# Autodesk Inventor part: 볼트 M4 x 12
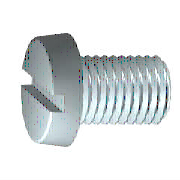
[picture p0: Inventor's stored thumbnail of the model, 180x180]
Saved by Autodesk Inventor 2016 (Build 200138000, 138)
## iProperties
Created: 2012-02
Part Number: 볼트 M4 x 12
Material: 강철, 연강
Description: 6각머리 태핑 나사
Document SubType Name: Modeling
Standard: KS B 1021
Designer: mduedu
Standards Organization: KS
Language: ko-KR
Size Designation: A  M 4 x 12
Categories: <MemberInstance><Categories><Category DisplayName="조임쇠" InternalName="e4da775c-781d-43d5-af7c-5136215cf5a6" Mnemonic="FSTN"><Category DisplayName="볼트" InternalN
Density: 1 g/cm^3
Appearance: 강철
IsCustomPart: 0
Author: mduedu
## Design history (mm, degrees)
body "Solid1"
revolve "본체" stored, may be unused: angle "d8" = 90 deg
sketch "스케치2"
  geometry: L1 (0, 0)-(0, 3.273) reference; L2 (-3.5, 0.6)-(3.5, 0.6); L3 (3.5, 0.6)-(3.5, -0.6); L4 (3.5, -0.6)-(-3.5, -0.6); L5 (-3.5, -0.6)-(-3.5, 0.6); L6 (-3.5, 0)-(3.5, 0); L7 (0, 0.6)-(0, -0.6); C1 r 3.5 at (0, 0) reference; 1 further point
  constraints: 12 end point, 5 midpoint, 2 parallel, 1 collinear, 1 horizontal, 1 perpendicular
  dimensions: "d11" = 1.2 distance of L4.end L2.start (= SBR); "d12" = 7 distance of L2.start L2.end (= KOD)
fillet "모깎기1" dims "d14" = 0.2 (= RR)
extrude "슬롯" cut sketch "스케치2" distance "d19" = 1.1 (= STI); taper "d20" = 0 deg
feature "스레드" dims "d15" = 10.6 (= GEL), "d16" = 0
chamfer "모따기1" distance "d17" = 0.42941 (= -0.5 x SPD + 0.5 x GD); stored, may be unused: second distance "d18" = 0.42952 (computed from GUL), angle "d36" = 45 deg
workplane "Work Plane1"
sketch "스케치1"
  geometry: L1 (-2.6, 0)-(12, 0); L2 (12, 0)-(12, 2); L3 (12, 2)-(1.4, 2); L4 (1.4, 2)-(0.97, 1.785); L5 (0.97, 1.785)-(0, 1.785); L6 (0, 1.785)-(0, 3.5); L7 (-5.52, 0)-(14.92, 0) reference; L8 (0, -0.7)-(0, 4.2) reference; L9 (-2.6, 0)-(-2.6, 3.273); L10 (0, 3.5)-(-2.6, 3.273); L11 (1.4, 2)-(0, 2)
  constraints: 18 end point, 4 parallel, 2 collinear, 2 perpendicular, 1 horizontal, 1 point on line
  dimensions: "d0" = 12 distance between parallel lines of L2 L6 (= NLG); "d1" = 10.6 distance from line of L3.end L2 (= GEL); "d2" = 0.42952 horizontal distance of L4.end L3.end (computed from GAL); "d3" = 2.6 distance from line of L1.start L6 (= KOH); "d4" = 4 diameter of L3 L1 (= GD); "d5" = 3.5705 diameter of L5 L1 (= BDM); "d9" = 7 diameter of L6.end L1 (= KOD); "d10" = 5 deg angle of L10 L1 (= KEWI)
other parameters: "GD" = 4 (= NND) [user parameter; used in 2 equation terms], "NLG" = 12 [user parameter; used in 1 equation term], "GEL" = 10.6 [user parameter; used in 2 equation terms], "KOD" = 7 [user parameter; used in 2 equation terms], "KOH" = 2.6 [user parameter; used in 1 equation term], "GAL" = 0.42941 (= 0.61345 x PTC) [user parameter; used in 1 equation term], "SPD" = 3.14117 (= NND - 1.2269 x PTC) [user parameter; used in 1 equation term], "BDM" = 3.5705 [user parameter; used in 1 equation term], "GUL" = 0.42941 (= 0.61345 x PTC) [user parameter; used in 1 equation term], "RR" = 0.2 [user parameter; used in 1 equation term], "d7" = 0, "SBR" = 1.2 [user parameter; used in 1 equation term], "STI" = 1.1 [user parameter; used in 1 equation term], "KEWI" = 5 deg [user parameter; used in 1 equation term], "d37" = 0, "d39" = 0, "PTC" = 0.7 [user parameter; used in 5 equation terms], "THREADDIA" = 4 [user parameter; used in 1 equation term], "TOA" = 30 deg [user parameter], "TPU" = 14.28571 (computed from PTC) [user parameter], "NND" = 4 [user parameter; used in 2 equation terms], "GD1" = 3.14117 (= THREADDIA - 1.2269 x PTC) [user parameter]
